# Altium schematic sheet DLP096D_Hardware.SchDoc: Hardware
size 431 x 279 mm; Date: Not shown in title block; ApprovedBy: Not shown in title block; CheckedBy: Not shown in title block; Author: Not shown in title block; CompanyName: Not shown in title block; Engineer: Not shown in title block; Organization: Not shown in title block; Address1: Not shown in title block; Address2: Not shown in title block; Address3: Not shown in title block; Address4: Not shown in title block; DocumentNumber: 10; Revision: Use project parameter SCH_Rev; SheetNumber: 10; SheetTotal: 10; PageSetup: Record=PageOptions¦CenterHorizontal=True¦CenterVertical=True¦PrintScale=1.00¦XCorrection=1.00¦YCorrection=1.00¦PrintKind=0¦BorderSize=5000000¦LeftOffset=0¦BottomOffset=0¦Orientation=2¦PaperLength=1000¦PaperWidth=1000¦Scale=100¦PaperSource=15¦PrintQuality=600¦MediaType=1¦DitherType=10¦PaperKind=Letter¦PrintScaleMode=1
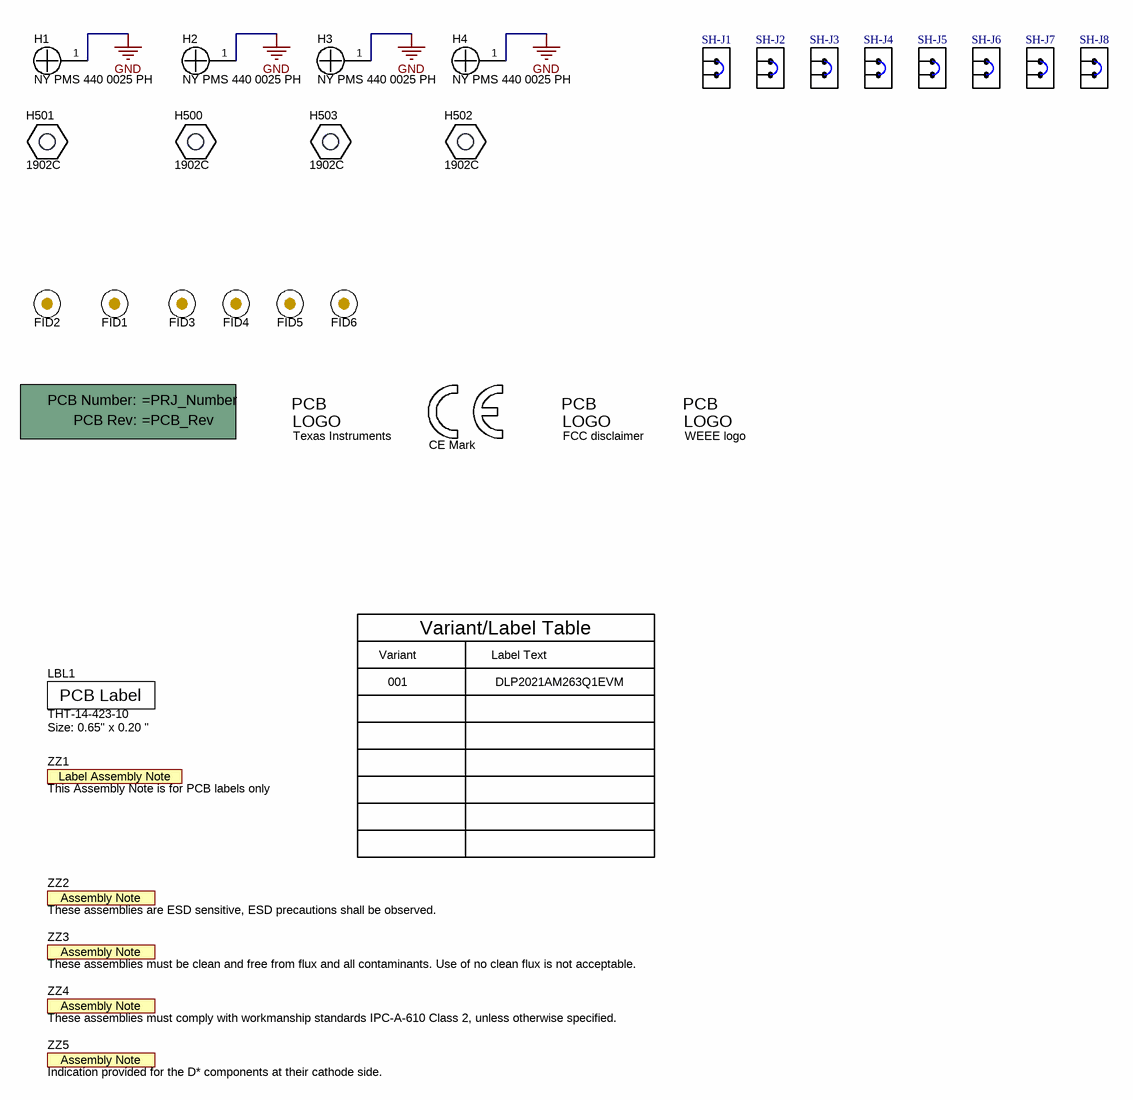
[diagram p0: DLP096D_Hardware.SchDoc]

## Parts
!PCB1  Printed Circuit Board  (value not drawn)  (mechanical)
FID1  Fiducial  [Fiducial10-20]  (value not drawn)
FID2  Fiducial  [Fiducial10-20]  (value not drawn)
FID3  Fiducial  [Fiducial10-20]  (value not drawn)
FID4  Fiducial  [Fiducial10-20]  (value not drawn)
FID5  Fiducial  [Fiducial10-20]  (value not drawn)
FID6  Fiducial  [Fiducial10-20]  (value not drawn)
H1  NY PMS 440 0025 PH  [NY PMS 440 0025 PH]
H2  NY PMS 440 0025 PH  [NY PMS 440 0025 PH]
H3  NY PMS 440 0025 PH  [NY PMS 440 0025 PH]
H4  NY PMS 440 0025 PH  [NY PMS 440 0025 PH]
H500  1902C  [Keystone_1902C]
H501  1902C  [Keystone_1902C]
H502  1902C  [Keystone_1902C]
H503  1902C  [Keystone_1902C]
LBL1  THT-14-423-10  Note: Size: 0.65" x 0.20 "  [Label_650x200]
Logo1  FCC disclaimer  [FCC_disclaimer]  (no BOM)
Logo2  Texas Instruments  [TI_Stacked_Overlay_Small]  (no BOM)
Logo3  WEEE logo  [WEEE_Minimum]  (no BOM)
Logo4  CE Mark  [CE_Mark_5mm]  (no BOM)
SH-J1  M7582-05  [Harwin_M7582-05]  (value not drawn)
SH-J2  M7582-05  [Harwin_M7582-05]  (value not drawn)
SH-J3  M7582-05  [Harwin_M7582-05]  (value not drawn)
SH-J4  M7582-05  [Harwin_M7582-05]  (value not drawn)
SH-J5  M7582-05  [Harwin_M7582-05]  (value not drawn)
SH-J6  M7582-05  [Harwin_M7582-05]  (value not drawn)
SH-J7  M7582-05  [Harwin_M7582-05]  (value not drawn)
SH-J8  M7582-05  [Harwin_M7582-05]  (value not drawn)
ZZ1  This Assembly Note is for PCB labels only  [AssemblyNoteLabel]  (no BOM)
ZZ2  These assemblies are ESD sensitive, ESD precautions shall be observed.  [AssemblyNote]  (no BOM)
ZZ3  These assemblies must be clean and free from flux and all contaminants. Use of no clean flux is not acceptable.  [AssemblyNote]  (no BOM)
ZZ4  These assemblies must comply with workmanship standards IPC-A-610 Class 2, unless otherwise specified.  [AssemblyNote]  (no BOM)
ZZ5  Indication provided for the D* components at their cathode side.  [AssemblyNote]  (no BOM)

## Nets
GND: H1.1 H2.1 H3.1 H4.1

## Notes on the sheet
- Variant
- Variant/Label Table
- Label Text
- 001
- DLP2021AM263Q1EVM

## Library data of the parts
!PCB1 = CMP-0003618-2: Manufacturer: Any
FID1-FID6 = CMP-0077181-1: Fiducial mark.  There is nothing to buy or mount.
H1-H4 = CMP-0003617-1: Machine Screw, Round, #4-40 x 1/4, Nylon, Philips panhead; Manufacturer: B&F Fastener Supply; CompType: Hardware
H500-H503 = CMP-0003610-1: Standoff, Hex, 0.5"L #4-40 Nylon; Manufacturer: Keystone; CompType: Hardware
LBL1 = CMP-0003625-1: Thermal Transfer Printable Labels, 0.650" W x 0.200" H - 10,000 per roll; Manufacturer: Brady; CompType: Label
Logo1 = CMP-0074847-1: FCC_disclaimer; Library Reference: Logo
Logo2 = CMP-0074838-1: Texas Instrument Corporate Signature; SymbolCreator: a0412235; Lib Reference: TI_Logo; Library Reference: Logo
Logo3 = CMP-0074769-1
Logo4 = CMP-0074844-1: SymbolCreator: a0412235
SH-J1-SH-J8 = CMP-0078738-1: Single Operation 2.54mm Pitch Open Top Jumper Socket; Manufacturer: Harwin
ZZ1 = CMP-0003616-3
ZZ2 = CMP-0077236-1
ZZ3 = CMP-0077237-1
ZZ4 ZZ5 = CMP-0077238-1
